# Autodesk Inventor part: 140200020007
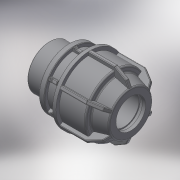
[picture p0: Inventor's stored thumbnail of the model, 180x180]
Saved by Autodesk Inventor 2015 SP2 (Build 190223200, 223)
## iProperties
Created: 2017-08
Part Number: 140200020007
Material: Generic
Description: PLASSON L.14 MALE ADAPTOR (SILVER) 20-3/4''
Document SubType Name: Modeling
Designer: KIM
Density: 1 g/cm^3
Appearance: Default
Author: KIM
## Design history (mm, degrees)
derived "140200.ipt"
feature "Solid1::140200.ipt"
tag "TaggingFeature1"
body "Solid1"
other parameters: "d4" = 15 deg, "d5" = 33, "d6" = 10.89, "d10" = 42, "d16" = 20.4, "d17" = 2.5, "d18" = 71, "d19" = 5.4, "d21" = 5.4, "d22" = 31.7292, "d24" = 2.5, "d25" = 37.8, "d26" = 31.5, "d27" = 2.5, "d28" = 135 deg, "d29" = 1.5, "d31" = 1, "d44" = 0.4, "d45" = 0.6, "d46" = 150 deg, "d49" = 2.1, "d50" = 0, "d51" = 1.26, "d52" = 0.84, "d53" = 45 deg, "d54" = 21, "d55" = 6.3, "d56" = 2.1, "d57" = 0, "d58" = 0.6, "d59" = 0.4, "d61" = 360 deg, "d63" = 26.441, "d64" = 16, "d65" = 18, "d66" = 35.69535, "R_" = 26.441, "E_" = 42, "H_" = 71, "l_2" = 18
